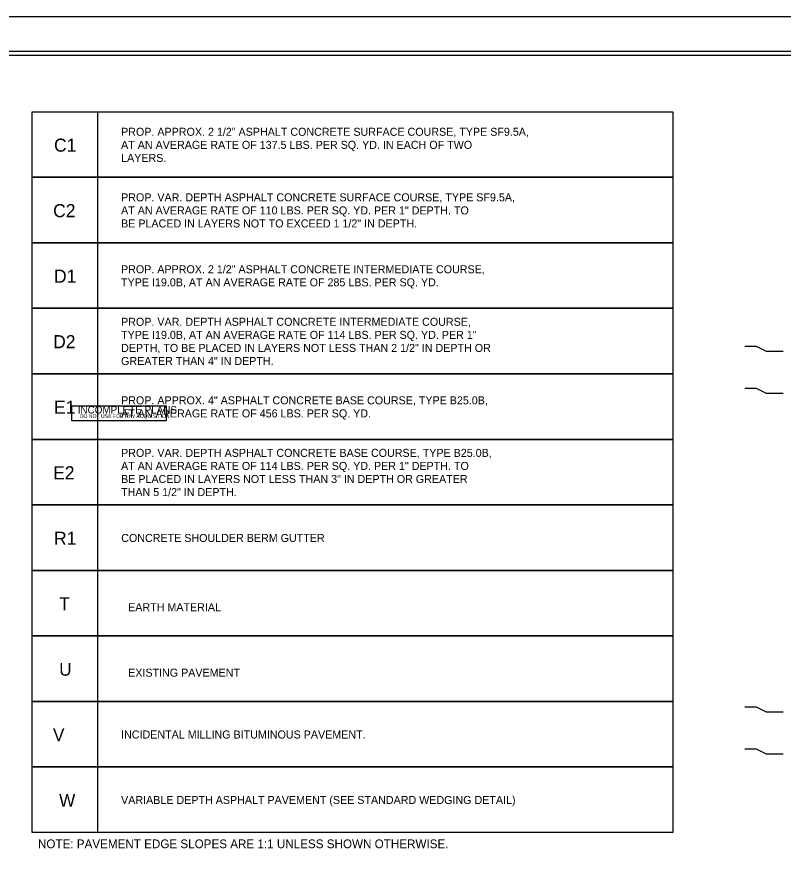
# Model space of a CAD drawing. Extents: x 573771 to 574316, y -53454 to -53190.
# Drawn here: x 573963.4 to 574083, y -53321.9 to -53189.5 of the extents above; entities that cross this region are included whole.
import ezdxf

# ---------------------------------------------------------------- set-up
doc = ezdxf.new("R2010")
doc.units = 0
for name, color, linetype in [('Prop Pavement Schedule Description CELL', 7, 'Continuous'), ('Sheet Cutting Line CELL', 7, 'Continuous'), ('Sheet Plot Border Inside CELL', 7, 'Continuous'), ('Sheet Plot Border Outside CELL', 7, 'Continuous'), ('Sheet Sticker Incomplete CELL', 7, 'Continuous'), ('Sheet Typical CELL', 7, 'Continuous'), ('Typical Slope Point Local CELL', 7, 'Continuous')]:
    doc.layers.add(name, color=color, linetype=linetype)

msp = doc.modelspace()

# ---------------------------------------------------------------- linework, layer by layer
at = {"layer": 'Prop Pavement Schedule Description CELL'}
for points in [[(573976.02, -53214.57), (573965.79, -53214.57), (573965.79, -53204.34), (574065.79, -53204.34), (574065.79, -53214.57), (573976.02, -53214.57), (573976.02, -53204.34)], [(573976.02, -53224.8), (573965.79, -53224.8), (573965.79, -53214.57), (574065.79, -53214.57), (574065.79, -53224.8), (573976.02, -53224.8), (573976.02, -53214.57)], [(573976.02, -53235.02), (573965.79, -53235.02), (573965.79, -53224.8), (574065.79, -53224.8), (574065.79, -53235.02), (573976.02, -53235.02), (573976.02, -53224.8)], [(573976.02, -53245.25), (573965.79, -53245.25), (573965.79, -53235.02), (574065.79, -53235.02), (574065.79, -53245.25), (573976.02, -53245.25), (573976.02, -53235.02)], [(573976.02, -53255.48), (573965.79, -53255.48), (573965.79, -53245.25), (574065.79, -53245.25), (574065.79, -53255.48), (573976.02, -53255.48), (573976.02, -53245.25)], [(573976.02, -53265.7), (573965.79, -53265.7), (573965.79, -53255.48), (574065.79, -53255.48), (574065.79, -53265.7), (573976.02, -53265.7), (573976.02, -53255.48)], [(573976.02, -53275.93), (573965.79, -53275.93), (573965.79, -53265.7), (574065.79, -53265.7), (574065.79, -53275.93), (573976.02, -53275.93), (573976.02, -53265.7)], [(573976.02, -53286.16), (573965.79, -53286.16), (573965.79, -53275.93), (574065.79, -53275.93), (574065.79, -53286.16), (573976.02, -53286.16), (573976.02, -53275.93)], [(573976.02, -53296.39), (573965.79, -53296.39), (573965.79, -53286.16), (574065.79, -53286.16), (574065.79, -53296.39), (573976.02, -53296.39), (573976.02, -53286.16)], [(573976.02, -53306.61), (573965.79, -53306.61), (573965.79, -53296.39), (574065.79, -53296.39), (574065.79, -53306.61), (573976.02, -53306.61), (573976.02, -53296.39)], [(573976.02, -53316.84), (573965.79, -53316.84), (573965.79, -53306.61), (574065.79, -53306.61), (574065.79, -53316.84), (573976.02, -53316.84), (573976.02, -53306.61)]]:
    msp.add_lwpolyline(points, dxfattribs=at)
at = {"layer": 'Sheet Cutting Line CELL'}
msp.add_line((574316.11, -53189.54), (573911.95, -53189.54), dxfattribs=at)
at = {"layer": 'Sheet Plot Border Inside CELL'}
msp.add_lwpolyline([(574315.03, -53194.93), (573915.07, -53194.93), (573915.07, -53448.15), (574315.03, -53448.15)], close=True, dxfattribs=at)
at = {"layer": 'Sheet Plot Border Outside CELL'}
msp.add_lwpolyline([(574316.11, -53189.54), (573911.95, -53189.54), (573911.95, -53453.54), (574316.11, -53453.54)], close=True, dxfattribs=at)
at = {"layer": 'Sheet Sticker Incomplete CELL'}
msp.add_lwpolyline([(573972, -53252.61), (573972, -53250.26), (573986.7, -53250.26), (573986.7, -53252.61)], close=True, dxfattribs=at)
at = {"layer": 'Sheet Typical CELL'}
msp.add_lwpolyline([(574312.03, -53195.54), (573952.03, -53195.54), (573952.03, -53447.54), (574312.03, -53447.54)], close=True, dxfattribs=at)
at = {"layer": 'Typical Slope Point Local CELL'}
for points in [[(574083.02, -53241.77), (574082.5, -53241.77), (574081.98, -53241.77), (574081.46, -53241.77), (574080.94, -53241.77), (574080.42, -53241.77), (574079.9, -53241.51), (574079.38, -53241.25), (574078.87, -53240.99), (574078.09, -53240.99), (574077.57, -53240.99), (574077.05, -53240.99)], [(574083.02, -53248.3), (574082.5, -53248.3), (574081.98, -53248.3), (574081.46, -53248.3), (574080.94, -53248.3), (574080.42, -53248.3), (574079.9, -53248.04), (574079.38, -53247.78), (574078.87, -53247.53), (574078.09, -53247.53), (574077.57, -53247.53), (574077.05, -53247.53)], [(574083.02, -53298.06), (574082.5, -53298.06), (574081.98, -53298.06), (574081.46, -53298.06), (574080.94, -53298.06), (574080.42, -53298.06), (574079.9, -53297.8), (574079.38, -53297.54), (574078.87, -53297.28), (574078.09, -53297.28), (574077.57, -53297.28), (574077.05, -53297.28)], [(574083.02, -53304.59), (574082.5, -53304.59), (574081.98, -53304.59), (574081.46, -53304.59), (574080.94, -53304.59), (574080.42, -53304.59), (574079.9, -53304.33), (574079.38, -53304.07), (574078.87, -53303.81), (574078.09, -53303.81), (574077.57, -53303.81), (574077.05, -53303.81)]]:
    msp.add_lwpolyline(points, dxfattribs=at)

# ---------------------------------------------------------------- texts
at = {"layer": 'Prop Pavement Schedule Description CELL'}
for s, height, p in [('PROP. APPROX. 2 1/2" ASPHALT CONCRETE SURFACE COURSE, TYPE SF9.5A, ', 1.25, (573979.67, -53208.09)), ('C1', 2.042, (573969.2, -53210.57)), ('AT AN AVERAGE RATE OF 137.5 LBS. PER SQ. YD. IN EACH OF TWO ', 1.25, (573979.67, -53210.13)), ('LAYERS.', 1.25, (573979.67, -53212.17)), ('PROP. VAR. DEPTH ASPHALT CONCRETE SURFACE COURSE, TYPE SF9.5A,', 1.25, (573979.67, -53218.32)), ('C2', 2.042, (573969.06, -53220.8)), ('AT AN AVERAGE RATE OF 110 LBS. PER SQ. YD. PER 1" DEPTH. TO', 1.25, (573979.67, -53220.36)), ('BE PLACED IN LAYERS NOT TO EXCEED 1 1/2" IN DEPTH.', 1.25, (573979.67, -53222.4)), ('D1', 2.042, (573969.2, -53231.02)), ('PROP. APPROX. 2 1/2" ASPHALT CONCRETE INTERMEDIATE COURSE,', 1.25, (573979.66, -53229.55)), ('TYPE I19.0B, AT AN AVERAGE RATE OF 285 LBS. PER SQ. YD.', 1.25, (573979.66, -53231.59)), ('PROP. VAR. DEPTH ASPHALT CONCRETE INTERMEDIATE COURSE,', 1.25, (573979.67, -53237.75)), ('TYPE I19.0B, AT AN AVERAGE RATE OF 114 LBS. PER SQ. YD. PER 1" ', 1.25, (573979.67, -53239.79)), ('D2', 2.042, (573969.06, -53241.25)), ('DEPTH, TO BE PLACED IN LAYERS NOT LESS THAN 2 1/2" IN DEPTH OR', 1.25, (573979.67, -53241.83)), ('GREATER THAN 4" IN DEPTH.', 1.25, (573979.67, -53243.87)), ('PROP. APPROX. 4" ASPHALT CONCRETE BASE COURSE, TYPE B25.0B,', 1.25, (573979.67, -53250.01)), ('E1', 2.042, (573969.2, -53251.48)), ('AT AN AVERAGE RATE OF 456 LBS. PER SQ. YD.', 1.25, (573979.67, -53252.05)), ('PROP. VAR. DEPTH ASPHALT CONCRETE BASE COURSE, TYPE B25.0B,', 1.25, (573979.67, -53258.21)), ('E2', 2.042, (573969.06, -53261.71)), ('AT AN AVERAGE RATE OF 114 LBS. PER SQ. YD. PER 1" DEPTH. TO', 1.25, (573979.67, -53260.25)), ('BE PLACED IN LAYERS NOT LESS THAN 3" IN DEPTH OR GREATER', 1.25, (573979.67, -53262.29)), ('THAN 5 1/2" IN DEPTH.', 1.25, (573979.67, -53264.33)), ('R1', 2.042, (573969.2, -53271.93)), ('CONCRETE SHOULDER BERM GUTTER', 1.25, (573979.69, -53271.49)), ('T', 2, (573970.01, -53282.14)), ('EARTH MATERIAL', 1.25, (573980.77, -53282.3)), ('U', 2, (573970.01, -53292.37)), ('EXISTING PAVEMENT', 1.25, (573980.77, -53292.52)), ('V ', 2, (573969.04, -53302.59)), ('INCIDENTAL MILLING BITUMINOUS PAVEMENT. ', 1.25, (573979.67, -53302.17)), ('W', 2, (573969.99, -53312.82)), ('VARIABLE DEPTH ASPHALT PAVEMENT (SEE STANDARD WEDGING DETAIL) ', 1.25, (573979.67, -53312.39)), ('NOTE: PAVEMENT EDGE SLOPES ARE 1:1 UNLESS SHOWN OTHERWISE.', 1.3604, (573966.69, -53319.29))]:
    msp.add_text(s, height=height, dxfattribs=at).set_placement(p)
at = {"layer": 'Sheet Sticker Incomplete CELL'}
for s, height, p in [('INCOMPLETE PLANS', 1.152, (573972.9, -53251.44)), ('DO NOT USE FOR R/W ACQUISITION', 0.576, (573973.22, -53252.13))]:
    msp.add_text(s, height=height, dxfattribs=at).set_placement(p)

doc.saveas('drawing.dxf')
